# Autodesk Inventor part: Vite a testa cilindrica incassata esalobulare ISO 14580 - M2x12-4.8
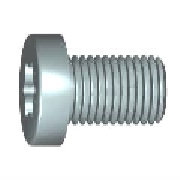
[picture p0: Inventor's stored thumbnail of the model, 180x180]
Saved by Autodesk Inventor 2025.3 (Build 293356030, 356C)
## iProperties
Created: 2024-01
Part Number: Vite a testa cilindrica incassata esalobulare ISO 14580 - M2x12-4.8
Material: Acciaio
Description: ISO 14580 - Viti a testa cilindrica incassata esalobulare - Seconda edizione
Document SubType Name: Modeling
Standard: 14580
Designer: R5800u
Standards Organization: ISO
Language: it-IT
Size Designation: M2x12-4.8
Categories: <MemberInstance><Categories><Category DisplayName="Elementi di fissaggio" InternalName="e4da775c-781d-43d5-af7c-5136215cf5a6" Mnemonic="FSTN"><Category DisplayN
Density: 7.85 g/cm^3
Appearance: Lamiera
IsCustomPart: 0
Author: R5800u
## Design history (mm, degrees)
revolve "Revolution1" stored, may be unused: angle "d4" = 90 deg
thread "Thread1" dims "d6" = 12 (= b), "d7" = 0
sketch "Sketch2" dims "d21" = 1.75 (= A_)
  geometry: L1 (-0.53, -0.306)-(-0.875, 0); L2 (0, 0)-(-0.53, -0.306); L3 (0, 0)-(-0.53, 0.306); L4 (-2.85, 0)-(2.85, 0) reference; L5 (-0.875, 0)-(-0.53, 0.306); A1 r 0.613 centre (0, 0) between (-0.53, -0.306) and (-0.53, 0.306); 2 further points
  constraints: 8 end point, 2 coincident, 2 point on circle, 1 centre point, 1 horizontal alignment, 1 point on line, 2 other
  dimensions: "d19" = 60 deg angle of L3 L2; "d20" = 30 deg angle of L3 L4 (= 0.5 x d19); "d26" = 1.225 diameter of A1 (= 0.7 x d21)
extrude "Extrusion1" cut sketch "Sketch2" distance "d27" = 0.84 (= t); taper "d28" = 0 deg
pattern_circular "Circular Pattern1" dims angle "d30" = 360 deg
fillet "Fillet2" dims "d32" = 0.2 (= v)
fillet "Fillet3" dims "d33" = 0.2 (= v)
fillet "Fillet5" dims "d35" = 0.1 (= r)
chamfer "Chamfer2" distance "d36" = 0.2 (= v); stored, may be unused: second distance "d37" = 2, angle "d38" = 45 deg
body "Solid1"
sketch "Sketch1"
  geometry: L1 (0, 0)-(12, 0); L2 (12, 0)-(12, 1); L3 (12, 1)-(0, 1); L4 (0, 1)-(0, 0); L5 (0, 0)-(-1.55, 0); L6 (-1.55, 0)-(-1.55, 1.9); L7 (-1.55, 1.9)-(0, 2.036); L8 (0, 2.036)-(0, 0)
  constraints: 16 end point, 3 parallel, 2 horizontal, 2 perpendicular
  dimensions: "d0" = 2 diameter of L3 L1 (= d); "d3" = 12 distance of L2.end L3.end (= l_); "d46" = 85 deg angle of L8 L7; "d47" = 1.55 distance between parallel lines of L8 L6 (= k); "d49" = 3.8 diameter of L6.end L1 (= dk)
other parameters: "A_" = 1.75 [user parameter; used in 1 equation term], "d" = 2 [user parameter; used in 2 equation terms], "dk" = 3.8 [user parameter; used in 1 equation term], "k" = 1.55 [user parameter; used in 1 equation term], "l_" = 12 [user parameter; used in 2 equation terms], "lg" = 0 [user parameter; used in 1 equation term], "t" = 0.84 [user parameter; used in 1 equation term], "w" = 0.55 [user parameter], "v" = 0.2 [user parameter; used in 3 equation terms], "r" = 0.1 [user parameter; used in 1 equation term], "da" = 2.6 [user parameter], "ds_" = 2 (= d) [user parameter], "ls" = 0 [user parameter], "b" = 12 (= l_ - lg) [user parameter; used in 1 equation term], "d42" = 0, "d43" = 0, "d44" = 0, "p" = 0.4 [user parameter]
